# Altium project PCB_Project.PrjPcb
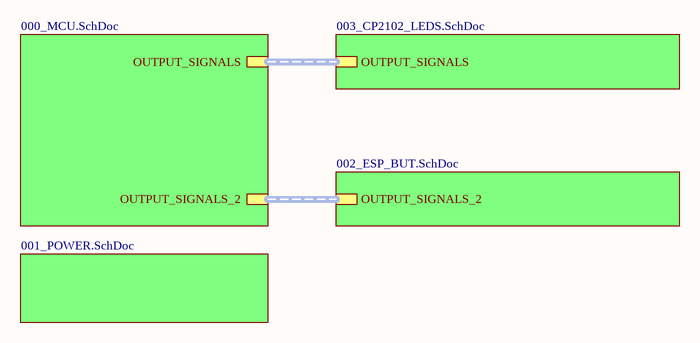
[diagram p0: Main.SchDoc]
5 sheets, 110 parts. Net scope: hierarchical (ports join the sheet entries above them; power ports are global).
Board file: PCB_DL.PcbDoc
Sheets:
  Main.SchDoc
    MCU = 000_MCU.SchDoc
    ESP = 002_ESP_BUT.SchDoc
    CP2102 = 003_CP2102_LEDS.SchDoc
    POWER = 001_POWER.SchDoc

## Sheet Main.SchDoc
size A4; SheetNumber: 1; SheetTotal: 5

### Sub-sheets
CP2102 = 003_CP2102_LEDS.SchDoc: OUTPUT_SIGNALS (harness OUTPUT_SIGNALS)
ESP = 002_ESP_BUT.SchDoc: OUTPUT_SIGNALS_2 (harness OUTPUT_SIGNALS_2)
MCU = 000_MCU.SchDoc: OUTPUT_SIGNALS_2 (harness OUTPUT_SIGNALS_2), OUTPUT_SIGNALS (harness OUTPUT_SIGNALS)
POWER = 001_POWER.SchDoc: no entries

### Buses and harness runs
harness sheet CP2102/OUTPUT_SIGNALS = sheet MCU/OUTPUT_SIGNALS
harness sheet ESP/OUTPUT_SIGNALS_2 = sheet MCU/OUTPUT_SIGNALS_2

## Sheet 000_MCU.SchDoc
size A4; SheetNumber: 2; SheetTotal: 5
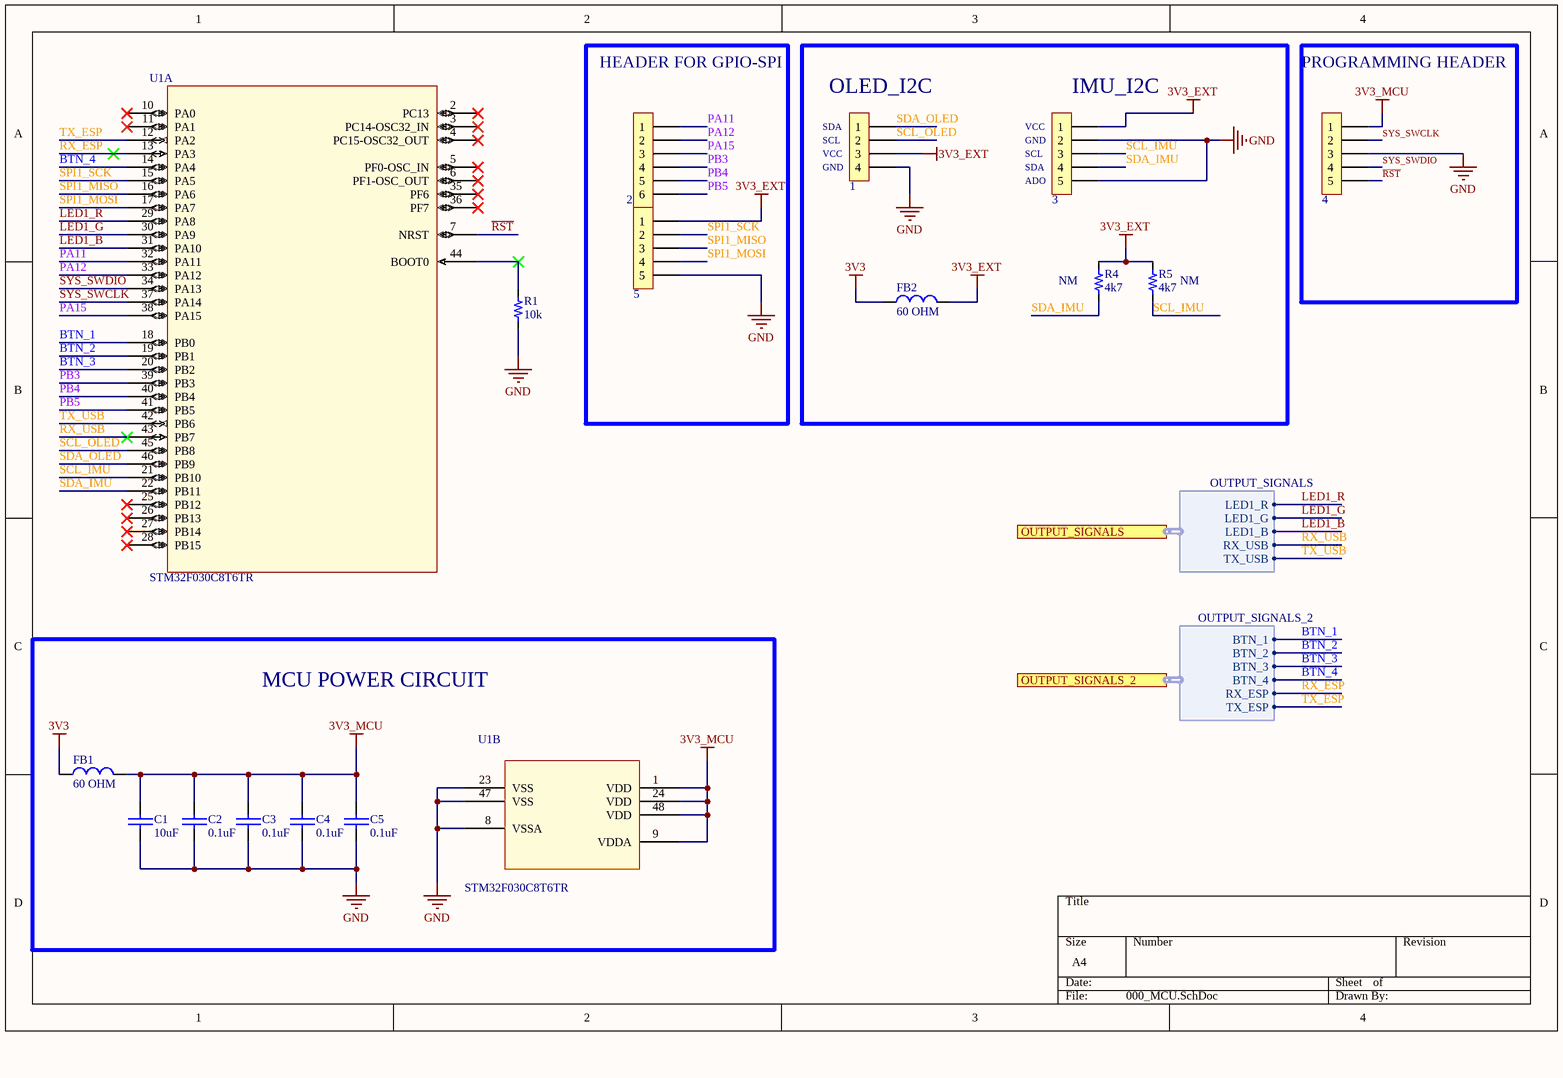
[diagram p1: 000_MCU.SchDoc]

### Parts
1  4x1  [H_4x1_TH_2.54mm]  (value not drawn)  (no BOM)
2  6x1  [H_6x1_TH_100mil]  (value not drawn)  (no BOM)
3  5x1  [H_5x1_TH_100mil]  (value not drawn)  (no BOM)
4  5x1  [H_5x1_TH_100mil]  (value not drawn)  (no BOM)
5  5x1  [H_5x1_TH_100mil]  (value not drawn)  (no BOM)
C1  value 10uF  [0603_cap]  (hidden comment: 10uF 10V)
C2  value 0.1uF  [0603_cap]  (hidden comment: 0.1uF 50V)
C3  value 0.1uF  [0603_cap]  (hidden comment: 0.1uF 50V)
C4  value 0.1uF  [0603_cap]  (hidden comment: 0.1uF 50V)
C5  value 0.1uF  [0603_cap]  (hidden comment: 0.1uF 50V)
FB1  value 60 OHM  [0603_fb]  (hidden comment: 60OHM 2A)
FB2  value 60 OHM  [0603_fb]  (hidden comment: 60OHM 2A)
R1  value 10k  [0603_res]  (hidden comment: 10k 1/10W)
R4  value 4k7  Usage: NM  [0603_res]  (hidden comment: 4k7 1/10W)
R5  value 4k7  Usage: NM  [0603_res]  (hidden comment: 4k7 1/10W)
U1  STM32F030C8T6TR  [LQFP48_7x7mm]  (parts A,B of 2)

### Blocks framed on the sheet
HEADER FOR GPIO-SPI: 2 5
PROGRAMMING HEADER: 4
MCU POWER CIRCUIT: C1-C5 FB1 U1

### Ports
OUTPUT_SIGNALS (harness OUTPUT_SIGNALS, see Main[2A], 003_CP2102_LEDS[2C]), OUTPUT_SIGNALS_2 (harness OUTPUT_SIGNALS_2, see Main[2B], 002_ESP_BUT[3A])

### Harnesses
OUTPUT_SIGNALS_2: BTN_1, BTN_2, BTN_3, BTN_4, RX_ESP, TX_ESP
OUTPUT_SIGNALS: LED1_R, LED1_G, LED1_B, RX_USB, TX_USB

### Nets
3V3: FB1.1 FB2.1
3V3_EXT: 1.3 3.1 5.1 FB2.2 R4.2 R5.2
3V3_MCU: 4.1 C1.1 C2.1 C3.1 C4.1 C5.1 FB1.2 U1.1(VDD) U1.9(VDDA) U1.24(VDD) U1.48(VDD)
GND: 1.4 3.2 3.5 4.3 5.5 C1.2 C2.2 C3.2 C4.2 C5.2 R1.1 U1.8(VSSA) U1.23(VSS) U1.47(VSS)
BTN_1: U1.18(PB0) ; port OUTPUT_SIGNALS_2.BTN_1
BTN_2: U1.19(PB1) ; port OUTPUT_SIGNALS_2.BTN_2
BTN_3: U1.20(PB2) ; port OUTPUT_SIGNALS_2.BTN_3
BTN_4: U1.14(PA4) ; port OUTPUT_SIGNALS_2.BTN_4
LED1_B: U1.31(PA10) ; port OUTPUT_SIGNALS.LED1_B
LED1_G: U1.30(PA9) ; port OUTPUT_SIGNALS.LED1_G
LED1_R: U1.29(PA8) ; port OUTPUT_SIGNALS.LED1_R
PA11: 2.1 U1.32(PA11)
PA12: 2.2 U1.33(PA12)
PA15: 2.3 U1.38(PA15)
PB3: 2.4 U1.39(PB3)
PB4: 2.5 U1.40(PB4)
PB5: 2.6 U1.41(PB5)
~{RST}: 4.5 U1.7(NRST)
RX_ESP: U1.13(PA3) ; port OUTPUT_SIGNALS_2.RX_ESP
RX_USB: U1.43(PB7) ; port OUTPUT_SIGNALS.RX_USB
SCL_IMU: 3.3 R5.1 U1.21(PB10)
SCL_OLED: 1.2 U1.45(PB8)
SDA_IMU: 3.4 R4.1 U1.22(PB11)
SDA_OLED: 1.1 U1.46(PB9)
SPI1_MISO: 5.3 U1.16(PA6)
SPI1_MOSI: 5.4 U1.17(PA7)
SPI1_SCK: 5.2 U1.15(PA5)
SYS_SWCLK: 4.2 U1.37(PA14)
SYS_SWDIO: 4.4 U1.34(PA13)
TX_ESP: U1.12(PA2) ; port OUTPUT_SIGNALS_2.TX_ESP
TX_USB: U1.42(PB6) ; port OUTPUT_SIGNALS.TX_USB
NetR1_2: R1.2 U1.44(BOOT0)

Not connected (* = marked no-connect by the designer): U1 2(PC13)* 3(PC14-OSC32_IN)* 4(PC15-OSC32_OUT)* 5(PF0-OSC_IN)* 6(PF1-OSC_OUT)* 10(PA0)* 11(PA1)* 25(PB12)* 26(PB13)* 27(PB14)* 28(PB15)* 35(PF6)* 36(PF7)*

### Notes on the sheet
- (near 1) OLED_I2C
- (near 3) IMU_I2C
- (near 1) SDA
- (near 1) SCL
- (near 1) VCC
- (near 1) GND
- (near 3) VCC
- (near 3) GND
- (near 3) SCL
- (near 3) SDA
- (near 3) ADO

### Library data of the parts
1 = H_Male_4x1_TH_100mil
2 = H_Male_6x1_TH_100mil
3-5 = H_Male_5x1_TH_100mil
C1 = Cap_10uF_0603_10V: 10V 10uF X5R ±10% 0603 Multilayer Ceramic Capacitors MLCC - SMD/SMT ROHS; Manufacturer: CCTC; Manufacturer Part Number: TCC0603X5R106K100CT
C2-C5 = Cap_0.1uF_0603_50V: 50V 100nF Y5V -20%~+80% 0603 Multilayer Ceramic Capacitors MLCC - SMD/SMT ROHS; Manufacturer: Walsin Tech Corp; Manufacturer Part Number: 0603F104Z500CT
FB1 FB2 = FB_60_0603_2A: 2A 1 100mΩ 60Ω@100MHz ±25% 0603 Ferrite Beads ROHS; Manufacturer: TAI-TECH; Manufacturer Part Number: HCB1608KF-600T20
R1 = Res_10k_0603_1/10W: RES SMD 10k OHM 5% 1/10W 0603; Manufacturer: FOJAN; Manufacturer Part Number: FRC0603J103TS
R4 R5 = Res_4k7_0603_1/10W: 100mW Thick Film Resistor 75V ±1% 4.7kΩ 0603 Chip Resistor - Surface Mount ROHS; Manufacturer: VO; Manufacturer Part Number: SCR0603F4K7
U1 = IC_STM32F030C8T6TR_LQFP48_7x7MM: IC MCU 32BIT 64KB FLASH 48LQFP; Manufacturer: STMicroelectronics

## Sheet 002_ESP_BUT.SchDoc
size A4; SheetNumber: 4; SheetTotal: 5
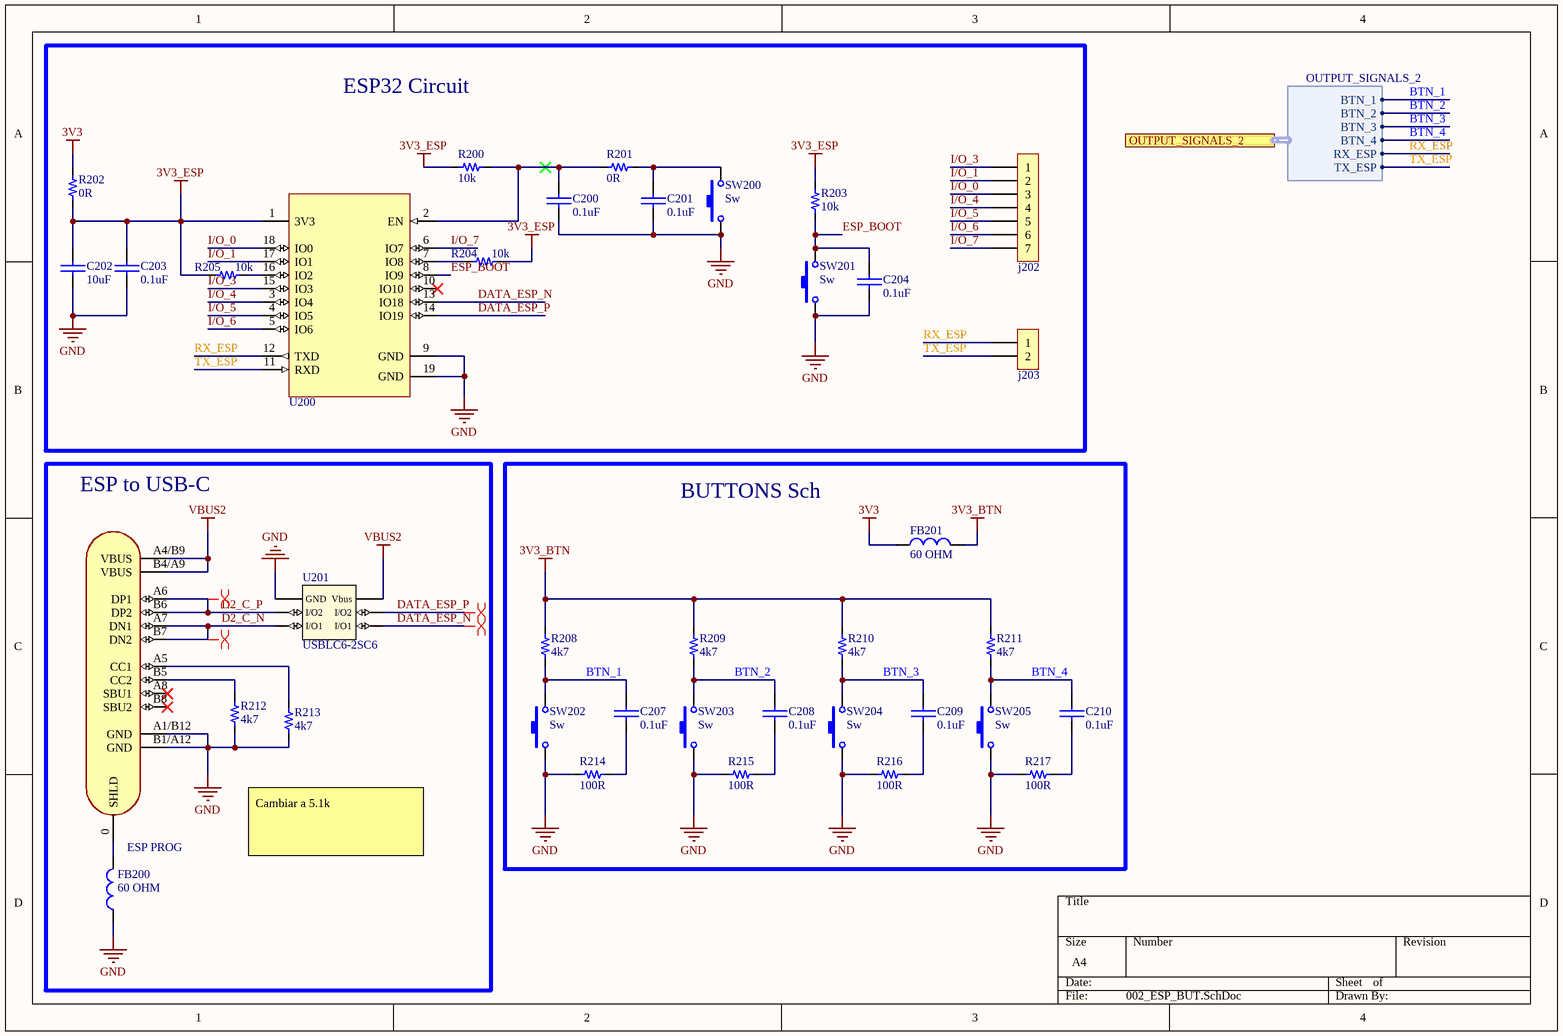
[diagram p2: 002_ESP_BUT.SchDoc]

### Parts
C200  value 0.1uF  [0603_cap]  (hidden comment: 0.1uF 50V)
C201  value 0.1uF  [0603_cap]  (hidden comment: 0.1uF 50V)
C202  value 10uF  [0603_cap]  (hidden comment: 10uF 10V)
C203  value 0.1uF  [0603_cap]  (hidden comment: 0.1uF 50V)
C204  value 0.1uF  [0603_cap]  (hidden comment: 0.1uF 50V)
C207  value 0.1uF  [0603_cap]  (hidden comment: 0.1uF 50V)
C208  value 0.1uF  [0603_cap]  (hidden comment: 0.1uF 50V)
C209  value 0.1uF  [0603_cap]  (hidden comment: 0.1uF 50V)
C210  value 0.1uF  [0603_cap]  (hidden comment: 0.1uF 50V)
ESP_PROG  USB C  [CON_USB_C_16P_RA]  (value not drawn)
FB200  value 60 OHM  [0603_fb]  (hidden comment: 60OHM 2A)
FB201  value 60 OHM  [0603_fb]  (hidden comment: 60OHM 2A)
j202  7x1  [H_7x1_TH_100mil]  (value not drawn)  (no BOM)
j203  2x1  [H_2x1_TH_100mil]  (value not drawn)  (no BOM)
R200  value 10k  [0603_res]  (hidden comment: 10k 1/10W)
R201  value 0R  [0603_res]  (hidden comment: 0R 1/10W)
R202  value 0R  [0603_res]  (hidden comment: 0R 1/10W)
R203  value 10k  [0603_res]  (hidden comment: 10k 1/10W)
R204  value 10k  [0603_res]  (hidden comment: 10k 1/10W)
R205  value 10k  [0603_res]  (hidden comment: 10k 1/10W)
R208  value 4k7  [0603_res]  (hidden comment: 4k7 1/10W)
R209  value 4k7  [0603_res]  (hidden comment: 4k7 1/10W)
R210  value 4k7  [0603_res]  (hidden comment: 4k7 1/10W)
R211  value 4k7  [0603_res]  (hidden comment: 4k7 1/10W)
R212  value 4k7  [0603_res]  (hidden comment: 4k7 1/10W)
R213  value 4k7  [0603_res]  (hidden comment: 4k7 1/10W)
R214  value 100R  [0603_res]  (hidden comment: 100R 1/10W)
R215  value 100R  [0603_res]  (hidden comment: 100R 1/10W)
R216  value 100R  [0603_res]  (hidden comment: 100R 1/10W)
R217  value 100R  [0603_res]  (hidden comment: 100R 1/10W)
SW200  Sw  [Sw_PUSH_4.5x4.5x5mm]
SW201  Sw  [Sw_PUSH_4.5x4.5x5mm]
SW202  Sw  [Sw_PUSH_4.5x4.5x5mm]
SW203  Sw  [Sw_PUSH_4.5x4.5x5mm]
SW204  Sw  [Sw_PUSH_4.5x4.5x5mm]
SW205  Sw  [Sw_PUSH_4.5x4.5x5mm]
U200  ESP32-C3-WROOM-02-N4  [ESP32-C3-WROOM-02-N4]  (value not drawn)
U201  USBLC6-2SC6  [SOT_23_6]

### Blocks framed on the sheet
ESP32 Circuit: C200-C204 j202 j203 R200-R205 SW200 SW201 U200
ESP to USB-C: ESP_PROG FB200 R212 R213 U201
BUTTONS Sch: C207-C210 FB201 R208-R211 R214-R217 SW202-SW205

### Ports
OUTPUT_SIGNALS_2 (harness OUTPUT_SIGNALS_2, see Main[2B], 000_MCU[3C])

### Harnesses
OUTPUT_SIGNALS_2: BTN_1, BTN_2, BTN_3, BTN_4, RX_ESP, TX_ESP

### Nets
3V3: FB201.1 R202.2
3V3_BTN: FB201.2 R208.2 R209.2 R210.2 R211.2
3V3_ESP: C202.1 C203.1 R200.1 R202.1 R203.2 R204.2 R205.1 U200.1(3V3)
GND: C200.2 C201.2 C202.2 C203.2 C204.2 ESP_PROG.A1/B12(GND) ESP_PROG.B1/A12(GND) FB200.1 R212.1 R213.1 R214.1 R215.1 R216.1 R217.1 SW200.1 SW201.1 SW202.1 SW203.1 SW204.1 SW205.1 U200.9(GND) U200.19(GND) U201.2(GND)
VBUS2: ESP_PROG.A4/B9(VBUS) ESP_PROG.B4/A9(VBUS) U201.5(Vbus)
BTN_1: C207.1 R208.1 SW202.2 ; port OUTPUT_SIGNALS_2.BTN_1
BTN_2: C208.1 R209.1 SW203.2 ; port OUTPUT_SIGNALS_2.BTN_2
BTN_3: C209.1 R210.1 SW204.2 ; port OUTPUT_SIGNALS_2.BTN_3
BTN_4: C210.1 R211.1 SW205.2 ; port OUTPUT_SIGNALS_2.BTN_4
D2_C_N: ESP_PROG.A7(DN1) ESP_PROG.B7(DN2) U201.1(I/O1)
D2_C_P: ESP_PROG.A6(DP1) ESP_PROG.B6(DP2) U201.3(I/O2)
DATA_ESP_N: U200.13(IO18) U201.6(I/O1)
DATA_ESP_P: U200.14(IO19) U201.4(I/O2)
ESP_BOOT: C204.1 R203.1 SW201.2 U200.8(IO9)
I/O_0: j202.3 U200.18(IO0)
I/O_1: j202.2 U200.17(IO1)
I/O_3: j202.1 U200.15(IO3)
I/O_4: j202.4 U200.3(IO4)
I/O_5: j202.5 U200.4(IO5)
I/O_6: j202.6 U200.5(IO6)
I/O_7: j202.7 U200.6(IO7)
RX_ESP: j203.1 U200.12(TXD) ; port OUTPUT_SIGNALS_2.RX_ESP
TX_ESP: j203.2 U200.11(RXD) ; port OUTPUT_SIGNALS_2.TX_ESP
NetC200_1: C200.1 R200.2 R201.2 U200.2(EN)
NetC201_1: C201.1 R201.1 SW200.2
NetC207_2: C207.2 R214.2
NetC208_2: C208.2 R215.2
NetC209_2: C209.2 R216.2
NetC210_2: C210.2 R217.2
NetESP_PROG_0: ESP_PROG.0(SHLD) FB200.2
NetESP_PROG_A5: ESP_PROG.A5(CC1) R213.2
NetESP_PROG_B5: ESP_PROG.B5(CC2) R212.2
NetR204_1: R204.1 U200.7(IO8)
NetR205_2: R205.2 U200.16(IO2)

Not connected (* = marked no-connect by the designer): ESP_PROG A8(SBU1)* B8(SBU2)*; U200 10(IO10)*

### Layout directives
differential pair; differential pair class USB_2.0: D2_C_N, D2_C_P, DATA_ESP_N, DATA_ESP_P

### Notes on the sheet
- Cambiar a 5.1k

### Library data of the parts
C200 C201 C203 C204 C207-C210 = Cap_0.1uF_0603_50V: as C2 on sheet 000_MCU
C202 = Cap_10uF_0603_10V: as C1 on sheet 000_MCU
ESP_PROG = CON_USB_TYPEC_16P: 3A USB 3.1 1 Surface Mount 16P Female -40℃~+85℃ Type-C SMD USB Connectors ROHS; Manufacturer: SHOU HAN; Manufacturer Part Number: TYPE-C-3.1-16PIN
FB200 FB201 = FB_60_0603_2A: as FB1 on sheet 000_MCU
j202 = H_Male_7x1_TH_100mil
j203 = H_Male_2x1_TH_100mil
R200 R203-R205 = Res_10k_0603_1/10W: as R1 on sheet 000_MCU
R201 R202 = Res_0R_0603_1/10W: RES SMD 0R OHM 5% 1/10W 0603; Manufacturer: FOJAN; Manufacturer Part Number: FRC0603P000 TS
R208-R213 = Res_4k7_0603_1/10W: as R4 on sheet 000_MCU
R214-R217 = Res_100R_0603_1/10W: RES SMD 100R OHM 5% 1/10W 0603; Manufacturer: FOJAN; Manufacturer Part Number: FRC0603J101 TS
SW200-SW205 = Sw_PUSH_4.5x4.5x5.0xmm: SWITCH TACTILE SPST-NO 0.05A 12V; Manufacturer: BZCN; Manufacturer Part Number: TSC015A05026A
U200 = MCU_ESP32-C3-WROOM-02-N4: RF TXRX MOD BT WIFI PCB TH SMD; Manufacturer: Espressif Systems
U201 = TVS_5.25V_2CH_SOT_23_6: TVS DIODE 5.25V 17V SOT23-6; Manufacturer: STMicroelectronics

## Sheet 003_CP2102_LEDS.SchDoc
size A4; SheetNumber: 5; SheetTotal: 5
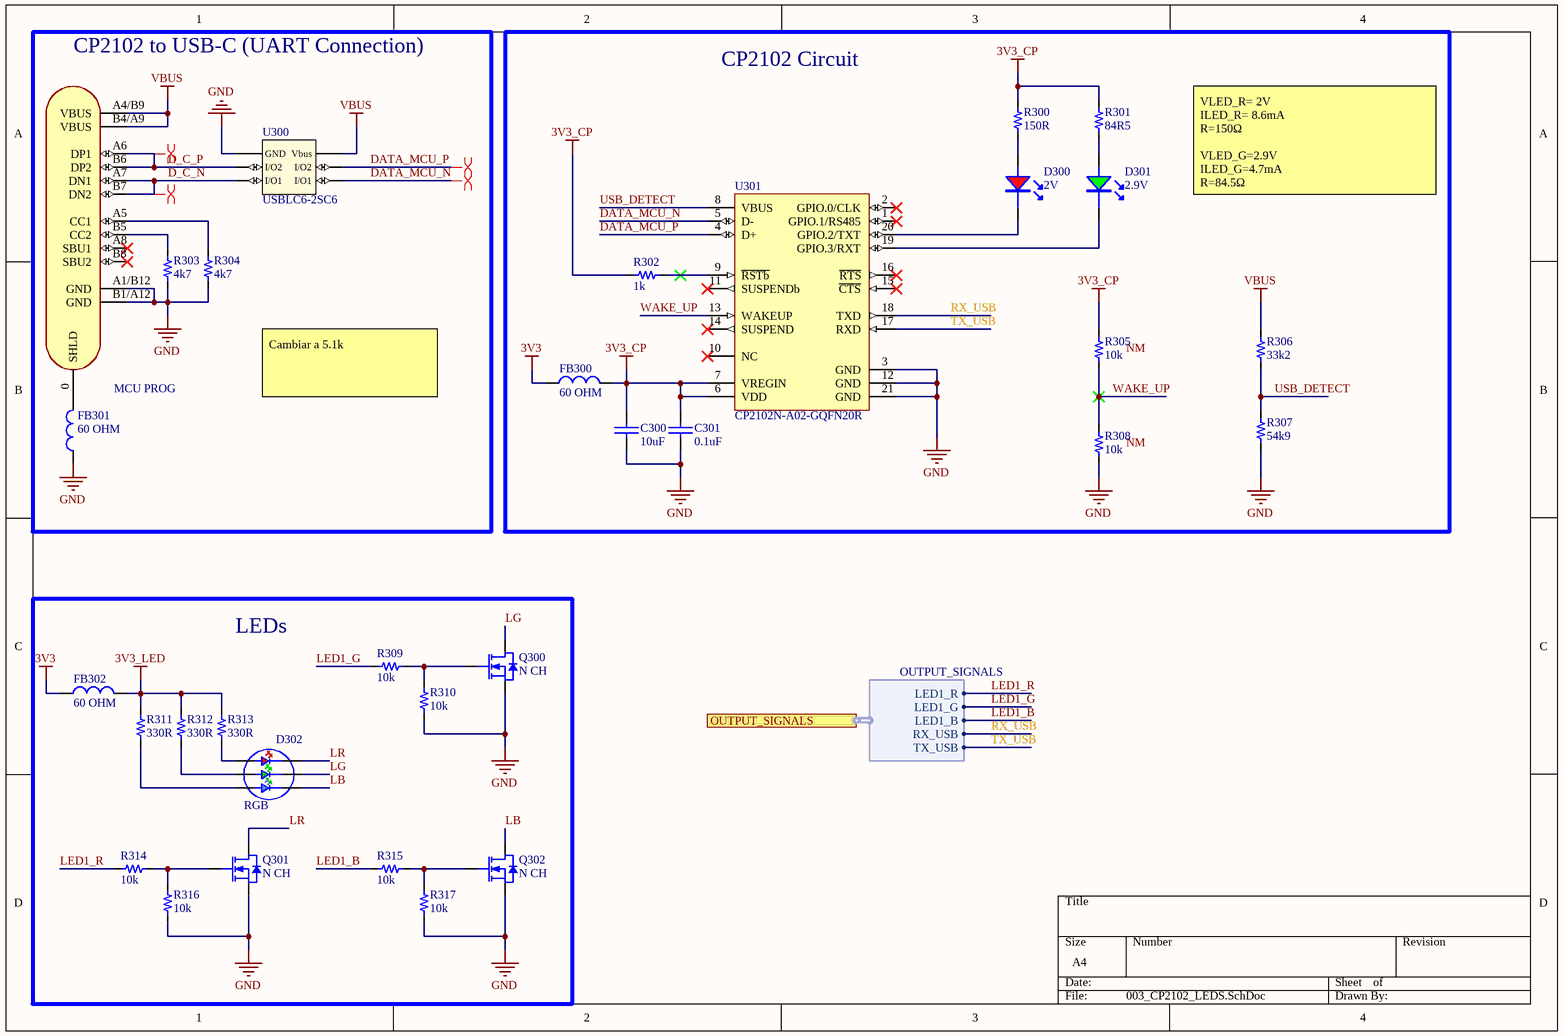
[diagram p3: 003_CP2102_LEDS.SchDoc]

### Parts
C300  value 10uF  [0603_cap]  (hidden comment: 10uF 10V)
C301  value 0.1uF  [0603_cap]  (hidden comment: 0.1uF 50V)
D300  2V  [0805_LED]
D301  2.9V  [0805_LED]
D302  RGB  [RGB_NS_3.5X3.7]
FB300  value 60 OHM  [0603_fb]  (hidden comment: 60OHM 2A)
FB301  value 60 OHM  [0603_fb]  (hidden comment: 60OHM 2A)
FB302  value 60 OHM  [0603_fb]  (hidden comment: 60OHM 2A)
MCU_PROG  USB C  [CON_USB_C_16P_RA]  (value not drawn)
Q300  N CH  [SOT_23_3]
Q301  N CH  [SOT_23_3]
Q302  N CH  [SOT_23_3]
R300  value 150R  [0603_res]  (hidden comment: 150R 1/10W)
R301  value 84R5  [0603_res]  (hidden comment: 84R5 1/10W)
R302  value 1k  [0603_res]  (hidden comment: 1k 1/10W)
R303  value 4k7  [0603_res]  (hidden comment: 4k7 1/10W)
R304  value 4k7  [0603_res]  (hidden comment: 4k7 1/10W)
R305  value 10k  Usage: NM  [0603_res]  (hidden comment: 10k 1/10W)
R306  value 33k2  [0603_res]  (hidden comment: 33k2 1/10W)
R307  value 54k9  [0603_res]  (hidden comment: 54k9 1/10W)
R308  value 10k  Usage: NM  [0603_res]  (hidden comment: 10k 1/10W)
R309  value 10k  [0603_res]  (hidden comment: 10k 1/10W)
R310  value 10k  [0603_res]  (hidden comment: 10k 1/10W)
R311  value 330R  [0603_res]  (hidden comment: 330R 1/10W)
R312  value 330R  [0603_res]  (hidden comment: 330R 1/10W)
R313  value 330R  [0603_res]  (hidden comment: 330R 1/10W)
R314  value 10k  [0603_res]  (hidden comment: 10k 1/10W)
R315  value 10k  [0603_res]  (hidden comment: 10k 1/10W)
R316  value 10k  [0603_res]  (hidden comment: 10k 1/10W)
R317  value 10k  [0603_res]  (hidden comment: 10k 1/10W)
U300  USBLC6-2SC6  [SOT_23_6]
U301  CP2102N-A02-GQFN20R  [WFQFN_20_EP_3X3MM]

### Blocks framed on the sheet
CP2102 to USB-C (UART Connection): FB301 MCU_PROG R303 R304 U300
CP2102 Circuit: C300 C301 D300 D301 FB300 R300-R302 R305-R308 U301
LEDs: D302 FB302 Q300-Q302 R309-R317

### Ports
OUTPUT_SIGNALS (harness OUTPUT_SIGNALS, see Main[2A], 000_MCU[3C])

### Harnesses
OUTPUT_SIGNALS: LED1_R, LED1_G, LED1_B, RX_USB, TX_USB

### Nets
3V3: FB300.1 FB302.1
3V3_CP: C300.1 C301.1 FB300.2 R300.2 R301.2 R302.1 R305.2 U301.6(VDD) U301.7(VREGIN)
3V3_LED: FB302.2 R311.2 R312.2 R313.2
GND: C300.2 C301.2 FB301.1 MCU_PROG.A1/B12(GND) MCU_PROG.B1/A12(GND) Q300.2(S) Q301.2(S) Q302.2(S) R303.1 R304.1 R307.1 R308.1 R310.1 R316.1 R317.1 U300.2(GND) U301.3(GND) U301.12(GND) U301.21(GND)
VBUS: MCU_PROG.A4/B9(VBUS) MCU_PROG.B4/A9(VBUS) R306.2 U300.5(Vbus)
D_C_N: MCU_PROG.A7(DN1) MCU_PROG.B7(DN2) U300.1(I/O1)
D_C_P: MCU_PROG.A6(DP1) MCU_PROG.B6(DP2) U300.3(I/O2)
DATA_MCU_N: U300.6(I/O1) U301.5(D-)
DATA_MCU_P: U300.4(I/O2) U301.4(D+)
LB: D302.1 Q302.3(D)
LED1_B: R315.1 ; port OUTPUT_SIGNALS.LED1_B
LED1_G: R309.1 ; port OUTPUT_SIGNALS.LED1_G
LED1_R: R314.1 ; port OUTPUT_SIGNALS.LED1_R
LG: D302.2 Q300.3(D)
LR: D302.3 Q301.3(D)
RX_USB: U301.18(TXD) ; port OUTPUT_SIGNALS.RX_USB
TX_USB: U301.17(RXD) ; port OUTPUT_SIGNALS.TX_USB
USB_DETECT: R306.1 R307.2 U301.8(VBUS)
WAKE_UP: R305.1 R308.2 U301.13(WAKEUP)
NetD300_1: D300.1(A) R300.1
NetD300_2: D300.2 U301.20(GPIO.2/TXT)
NetD301_1: D301.1(A) R301.1
NetD301_2: D301.2 U301.19(GPIO.3/RXT)
NetD302_4: D302.4 R313.1
NetD302_5: D302.5 R312.1
NetD302_6: D302.6 R311.1
NetFB301_2: FB301.2 MCU_PROG.0(SHLD)
NetMCU_PROG_A5: MCU_PROG.A5(CC1) R304.2
NetMCU_PROG_B5: MCU_PROG.B5(CC2) R303.2
NetQ300_1: Q300.1(G) R309.2 R310.2
NetQ301_1: Q301.1(G) R314.2 R316.2
NetQ302_1: Q302.1(G) R315.2 R317.2
NetR302_2: R302.2 U301.9(~{RSTb})

Not connected (* = marked no-connect by the designer): MCU_PROG A8(SBU1)* B8(SBU2)*; U301 1(GPIO.1/RS485)* 2(GPIO.0/CLK)* 10(NC)* 11(SUSPENDb)* 14(SUSPEND)* 15(~{CTS})* 16(~{RTS})*

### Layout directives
differential pair; differential pair class USB_2.0: D_C_N, D_C_P, DATA_MCU_N, DATA_MCU_P

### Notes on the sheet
- VLED_R= 2V
  ILED_R= 8.6mA
  R=150Ω
  VLED_G=2.9V
  ILED_G=4.7mA
  R=84.5Ω
- Cambiar a 5.1k

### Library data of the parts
C300 = Cap_10uF_0603_10V: as C1 on sheet 000_MCU
C301 = Cap_0.1uF_0603_50V: as C2 on sheet 000_MCU
D300 = LED_0805_RED: LED RED CLEAR 0805 SMD; Manufacturer: XINGLIGHT; Manufacturer Part Number: XL-2012SURC
D301 = LED_0805_Green: LED GREEN CLEAR 0805 SMD; Manufacturer: XINGLIGHT; Manufacturer Part Number: XL-2012UGC
D302 = LED_RGB_3535_SMD: -30℃~+85℃ RGB 110° 3535(mm) Light Emitting Diodes (LED) ROHS; Manufacturer: Foshan NationStar Optoelectronics; Manufacturer Part Number: RS-3535MWAM
FB300-FB302 = FB_60_0603_2A: as FB1 on sheet 000_MCU
MCU_PROG = CON_USB_TYPEC_16P: as ESP_PROG on sheet 002_ESP_BUT
Q300-Q302 = Q_NFET_20V_3.2A_SOT23: MOSFET N-CH 20V SOT23; Manufacturer: Doeshare; Manufacturer Part Number: DN2302S
R300 = Res_150R_0603_1/10W: 100mW Thick Film Resistor 75V ±100ppm/℃ ±1% 150Ω 0603 Chip Resistor - Surface Mount ROHS; Manufacturer: RALEC; Manufacturer Part Number: RTT031500FTP
R301 = Res_84R5_0603_1/10W: 100mW Thick Film Resistor 50V ±100ppm/℃ ±1% 84.5Ω 0603 Chip Resistor - Surface Mount ROHS; Manufacturer: LIZ Elec; Manufacturer Part Number: CR0603FA84R5G
R302 = Res_1k_0603_1/10W: RES SMD 1k OHM 5% 1/10W 0603; Manufacturer: FOJAN; Manufacturer Part Number: FRC0603J102 TS
R303 R304 = Res_4k7_0603_1/10W: as R4 on sheet 000_MCU
R305 R308-R310 R314-R317 = Res_10k_0603_1/10W: as R1 on sheet 000_MCU
R306 = Res_33k2_0603_1/10W: 100mW Thick Film Resistor 75V ±100ppm/℃ ±1% 33.2kΩ 0603 Chip Resistor - Surface Mount ROHS; Manufacturer: YAGEO; Manufacturer Part Number: RC0603FR-0733K2L
R307 = Res_54k9_0603_1/10W: 100mW Thick Film Resistor 75V ±100ppm/℃ ±1% 54.9kΩ 0603 Chip Resistor - Surface Mount ROHS; Manufacturer: YAGEO; Manufacturer Part Number: RC0603FR-0754K9L
R311-R313 = Res_330R_0603_1/10W: RES SMD 330R OHM 5% 1/10W 0603; Manufacturer: FOJAN; Manufacturer Part Number: FRC0603J331 TS
U300 = TVS_5.25V_2CH_SOT_23_6: as U201 on sheet 002_ESP_BUT
U301 = IC_SGL_USB2UART-BRIDGE_20QFN: IC USB TO UART BRIDGE QFN20; Manufacturer: Silicon Labs

## Sheet 001_POWER.SchDoc
size A4; SheetNumber: 3; SheetTotal: 5
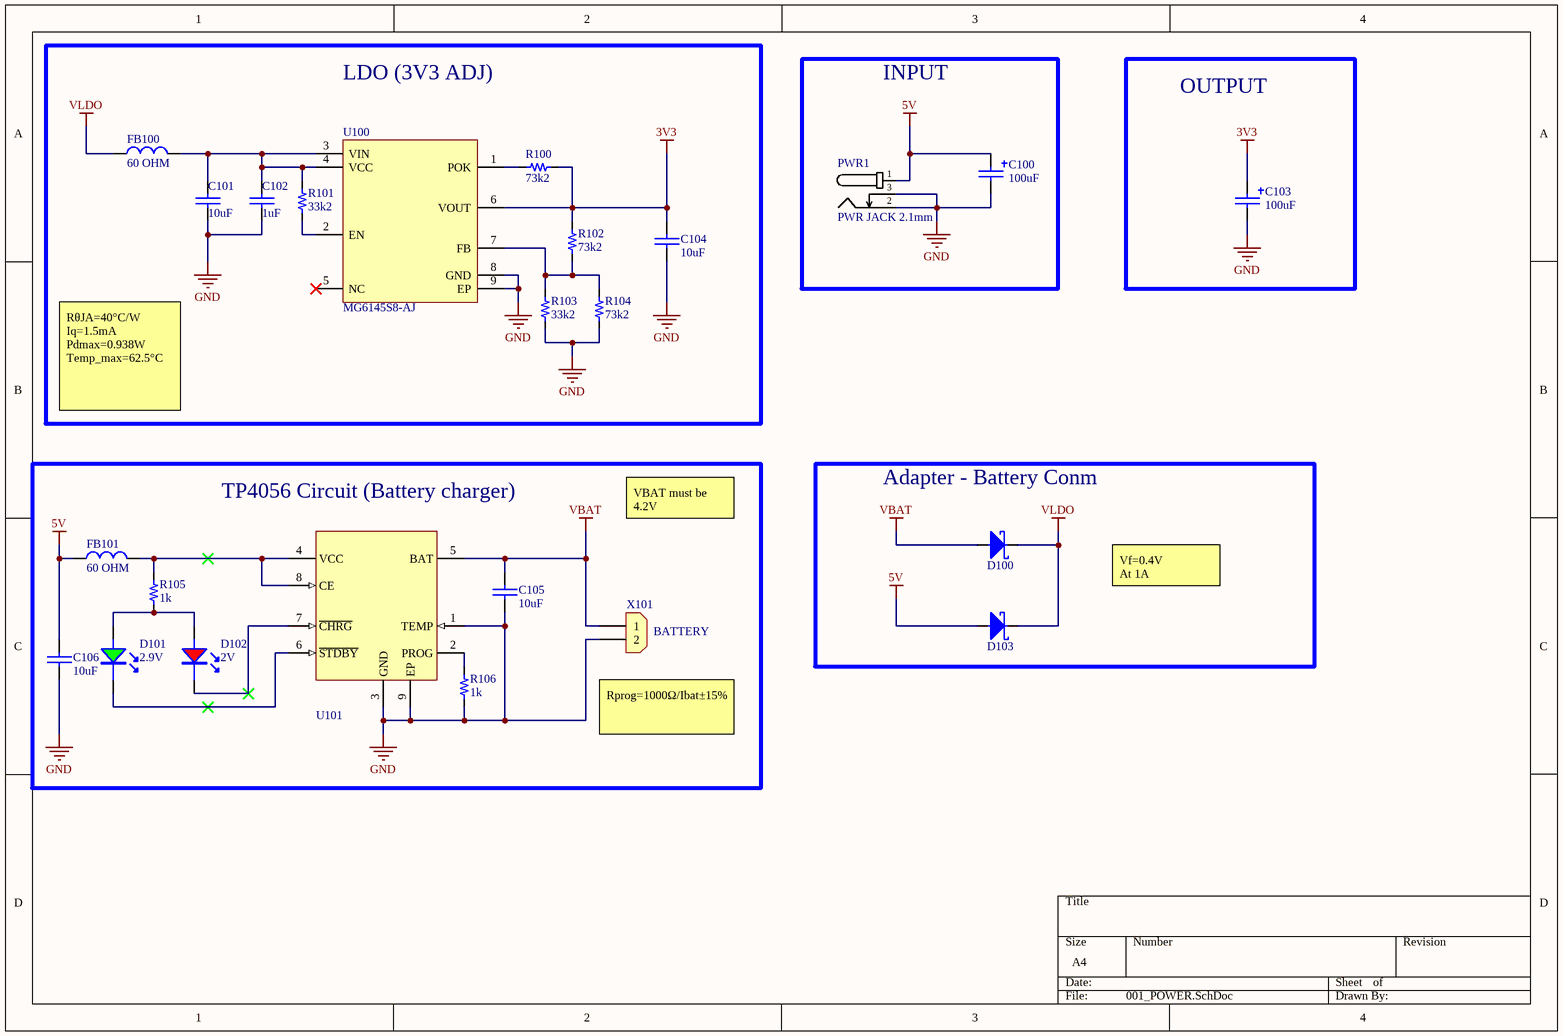
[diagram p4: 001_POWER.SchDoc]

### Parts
C100  value 100uF  [CAP_TH_2.5MM_6.3*12MM]  (hidden comment: 100uF 35V)
C101  value 10uF  [0603_cap]  (hidden comment: 10uF 10V)
C102  value 1uF  [0603_cap]  (hidden comment: 1uF 50V)
C103  value 100uF  [CAP_TH_2.5MM_6.3*12MM]  (hidden comment: 100uF 35V)
C104  value 10uF  [0603_cap]  (hidden comment: 10uF 10V)
C105  value 10uF  [0603_cap]  (hidden comment: 10uF 10V)
C106  value 10uF  [0603_cap]  (hidden comment: 10uF 10V)
D100  30V 3A  [SMA]  (value not drawn)
D101  2.9V  [0805_LED]
D102  2V  [0805_LED]
D103  30V 3A  [SMA]  (value not drawn)
FB100  value 60 OHM  [0603_fb]  (hidden comment: 60OHM 2A)
FB101  value 60 OHM  [0603_fb]  (hidden comment: 60OHM 2A)
PWR1  PWR JACK 2.1mm  [CON_POWER_BARREL_2.1MM_3CONN]
R100  value 73k2  [0603_res]  (hidden comment: 73k2 1/10W)
R101  value 33k2  [0603_res]  (hidden comment: 33k2 1/10W)
R102  value 73k2  [0603_res]  (hidden comment: 73k2 1/10W)
R103  value 33k2  [0603_res]  (hidden comment: 33k2 1/10W)
R104  value 73k2  [0603_res]  (hidden comment: 73k2 1/10W)
R105  value 1k  [0603_res]  (hidden comment: 1k 1/10W)
R106  value 1k  [0603_res]  (hidden comment: 1k 1/10W)
U100  MG6145S8-AJ  [LDO_3A_ADJ]
U101  4.2V 1A  [SOIC_8_3.9mm_EP]  (value not drawn)
X101  Connector 2pos  [CON_2x1_TH_2MM]  (value not drawn)

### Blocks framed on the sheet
LDO (3V3 ADJ): C101 C102 C104 FB100 R100-R104 U100
INPUT: C100 PWR1
OUTPUT: C103
TP4056 Circuit (Battery charger): C105 C106 D101 D102 FB101 R105 R106 U101 X101
Adapter - Battery Conm: D100 D103

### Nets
3V3: C103.1 C104.1 R100.1 R102.1 U100.6(VOUT)
5V: C100.1 C106.1 D103.2 FB101.1 PWR1.1
GND: C100.2 C101.2 C102.2 C103.2 C104.2 C105.2 C106.2 PWR1.2 PWR1.3 R103.2 R104.1 R106.2 U100.8(GND) U100.9(EP) U101.1(TEMP) U101.3(GND) U101.9(EP) X101.2
VBAT: C105.1 D100.2 U101.5(BAT) X101.1
VLDO: D100.1 D103.1 FB100.1
NetC101_1: C101.1 C102.1 FB100.2 R101.2 U100.3(VIN) U100.4(VCC)
NetD101_1: D101.1(A) D102.1(A) R105.2
NetD101_2: D101.2 U101.6(~{STDBY})
NetD102_2: D102.2 U101.7(~{CHRG})
NetFB101_2: FB101.2 R105.1 U101.4(VCC) U101.8(CE)
NetR100_2: R100.2 U100.1(POK)
NetR101_1: R101.1 U100.2(EN)
NetR102_2: R102.2 R103.1 R104.2 U100.7(FB)
NetR106_1: R106.1 U101.2(PROG)

Not connected (* = marked no-connect by the designer): U100 5(NC)*

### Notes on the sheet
- RθJA=40°C/W
  Iq=1.5mA
  Pdmax=0.938W
  Temp_max=62.5°C
- VBAT must be 4.2V
- Vf=0.4V
  At 1A
- (near X101) BATTERY
- (near X101) Rprog=1000Ω/Ibat±15%

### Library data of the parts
C100 C103 = Cap_100uF_ALU_TH_35V: 100uF 35V ±20% Plugin,D6.3xL12mm Aluminum Electrolytic Capacitors - Leaded ROHS; Manufacturer: HRK; Manufacturer Part Number: 35V100uF CD110
C101 C104-C106 = Cap_10uF_0603_10V: as C1 on sheet 000_MCU
C102 = Cap_1uF_0603_50V: 50V 1uF X5R ±10% 0603 Multilayer Ceramic Capacitors MLCC - SMD/SMT ROHS; Manufacturer: Samsung Electro-Mechanics; Manufacturer Part Number: CL10A105KB8NNNC
D100 D103 = D_Schottky_40V_3A_SMA: 40V Independent 3A 550mV@3A SMA Schottky Diodes ROHS; Manufacturer: TDSEMIC; Manufacturer Part Number: SS34-TD
D101 = LED_0805_Green: as D301 on sheet 003_CP2102_LEDS
D102 = LED_0805_RED: as D300 on sheet 003_CP2102_LEDS
FB100 FB101 = FB_60_0603_2A: as FB1 on sheet 000_MCU
PWR1 = Con_Power_Jack_2.1mm_3pins: CONN PWR JACK 2X5.5MM SOLDER; Manufacturer: HCTL; Manufacturer Part Number: HC-DC-005-2.0T
R100 R102 R104 = Res_73k2_0603_1/10W: 100mW Thick Film Resistor 75V ±100ppm/℃ ±1% 73.2kΩ 0603 Chip Resistor - Surface Mount ROHS; Manufacturer: YAGEO; Manufacturer Part Number: RC0603FR-0773K2L
R101 R103 = Res_33k2_0603_1/10W: as R306 on sheet 003_CP2102_LEDS
R105 R106 = Res_1k_0603_1/10W: as R302 on sheet 003_CP2102_LEDS
U100 = LDO_3A_ADJ: 3A Adjustable 800mV~3.3V Positive 5.5V ESOP-8 Voltage Regulators - Linear, Low Drop Out (LDO) Regulators ROHS; Manufacturer: Megain
U101 = IC_BAT_CHG_4.2V_1A: -300mV~8V Lithium-ion/Polymer 1 1A ESOP-8 Battery Management ROHS; Manufacturer: YONGYUTAI; Manufacturer Part Number: TP4056
X101 = Con_2x1_TH_JST_2MM: 2POS 2MM; Manufacturer: JST; Manufacturer Part Number: S2B-PH-K-S(LF)(SN)

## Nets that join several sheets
3V3: 000_MCU (FB1.1 FB2.1), 002_ESP_BUT (FB201.1 R202.2), 003_CP2102_LEDS (FB300.1 FB302.1), 001_POWER (5 pins)
GND: 000_MCU (14 pins), 002_ESP_BUT (23 pins), 003_CP2102_LEDS (19 pins), 001_POWER (18 pins)
BTN_1: 000_MCU (U1.18), 002_ESP_BUT (C207.1 R208.1 SW202.2)
BTN_2: 000_MCU (U1.19), 002_ESP_BUT (C208.1 R209.1 SW203.2)
BTN_3: 000_MCU (U1.20), 002_ESP_BUT (C209.1 R210.1 SW204.2)
BTN_4: 000_MCU (U1.14), 002_ESP_BUT (C210.1 R211.1 SW205.2)
LED1_B: 000_MCU (U1.31), 003_CP2102_LEDS (R315.1)
LED1_G: 000_MCU (U1.30), 003_CP2102_LEDS (R309.1)
LED1_R: 000_MCU (U1.29), 003_CP2102_LEDS (R314.1)
RX_ESP: 000_MCU (U1.13), 002_ESP_BUT (j203.1 U200.12)
RX_USB: 000_MCU (U1.43), 003_CP2102_LEDS (U301.18)
TX_ESP: 000_MCU (U1.12), 002_ESP_BUT (j203.2 U200.11)
TX_USB: 000_MCU (U1.42), 003_CP2102_LEDS (U301.17)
